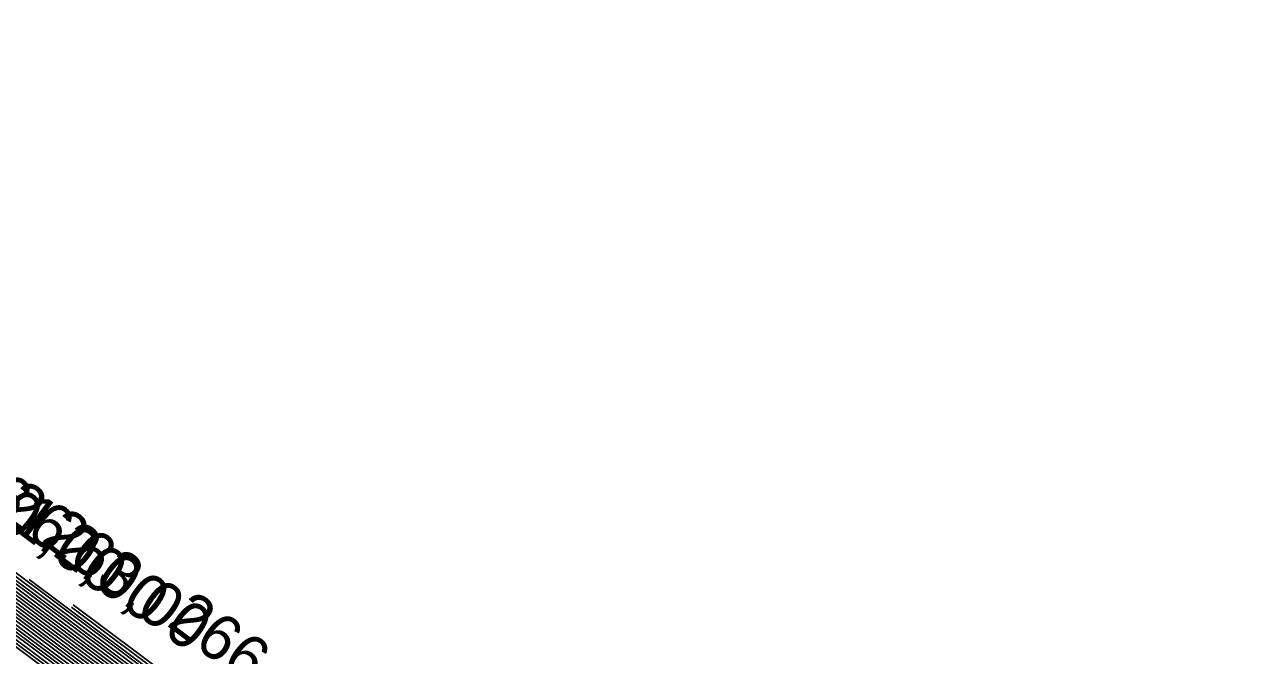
# Model space of a CAD drawing. Extents: x -500397 to -496810, y -1135552 to -1132176.
# Drawn here: x -500159.2 to -500105.5, y -1134894 to -1134866.4 of the extents above; entities that cross this region are included whole.
import ezdxf

# ---------------------------------------------------------------- set-up
doc = ezdxf.new("R2010")
doc.units = 0
doc.layers.add('30', color=7, linetype='Continuous')
doc.layers.add('40', color=7, linetype='Continuous')

msp = doc.modelspace()

# ---------------------------------------------------------------- linework, layer by layer
at = {"layer": '30'}
for points in [[(-500197.665, -1134865.141), (-500015.742, -1135001.134), (-500014.028, -1135002.405), (-500012.303, -1135003.66), (-500010.568, -1135004.901), (-500008.822, -1135006.127), (-500005.809, -1135008.224)], [(-500197.588, -1134865.037), (-500014.023, -1135002.258), (-500012.301, -1135003.534), (-500010.568, -1135004.795), (-500008.825, -1135006.042), (-500007.071, -1135007.274), (-500005.774, -1135008.177)], [(-500005.737, -1135008.127), (-500007.082, -1135007.183), (-500008.833, -1135005.931), (-500010.574, -1135004.664), (-500012.303, -1135003.382), (-500197.51, -1134864.934)], [(-500192.14, -1134868.786), (-500010.584, -1135004.506), (-500008.846, -1135005.794), (-500007.098, -1135007.066), (-500005.694, -1135008.07)], [(-500025.994, -1134992.179), (-500189.989, -1134869.587)], [(-500189.912, -1134869.484), (-500029.358, -1134989.503)], [(-500190.299, -1134870.002), (-500008.864, -1135005.63), (-500007.119, -1135006.923), (-500005.641, -1135007.999)], [(-500190.221, -1134869.898), (-500015.905, -1135000.206)], [(-500019.268, -1134997.53), (-500190.144, -1134869.795)], [(-500022.631, -1134994.854), (-500190.067, -1134869.691)], [(-500179.25, -1134877.293), (-500029.28, -1134989.4)], [(-500046.173, -1134976.126), (-500177.176, -1134878.197)], [(-500177.408, -1134878.508), (-500029.203, -1134989.296)], [(-500177.331, -1134878.404), (-500039.447, -1134981.477)], [(-500042.81, -1134978.801), (-500177.253, -1134878.301)], [(-500170.042, -1134883.369), (-500046.096, -1134976.022)], [(-500052.9, -1134970.775), (-500169.965, -1134883.265)], [(-500052.822, -1134970.671), (-500166.359, -1134885.799)], [(-500164.362, -1134886.807), (-500066.353, -1134960.073)], [(-500164.517, -1134887.014), (-500052.745, -1134970.568)], [(-500062.989, -1134962.748), (-500164.44, -1134886.91)], [(-500066.275, -1134959.969), (-500158.993, -1134890.66)], [(-500157.151, -1134891.875), (-500066.198, -1134959.865)], [(-500157.074, -1134891.771), (-500076.442, -1134952.046)]]:
    msp.add_lwpolyline(points, dxfattribs=at)

# ---------------------------------------------------------------- texts
at = {"layer": '40'}
for s, p in [('259,00', (-500165.93, -1134884.139)), ('261,00', (-500162.247, -1134886.57)), ('262,00', (-500160.405, -1134887.785)), ('263,00', (-500158.564, -1134889)), ('266,00', (-500153.039, -1134892.645))]:
    msp.add_text(s, height=2, rotation=323.2207, dxfattribs=at).set_placement(p)

doc.saveas('drawing.dxf')
